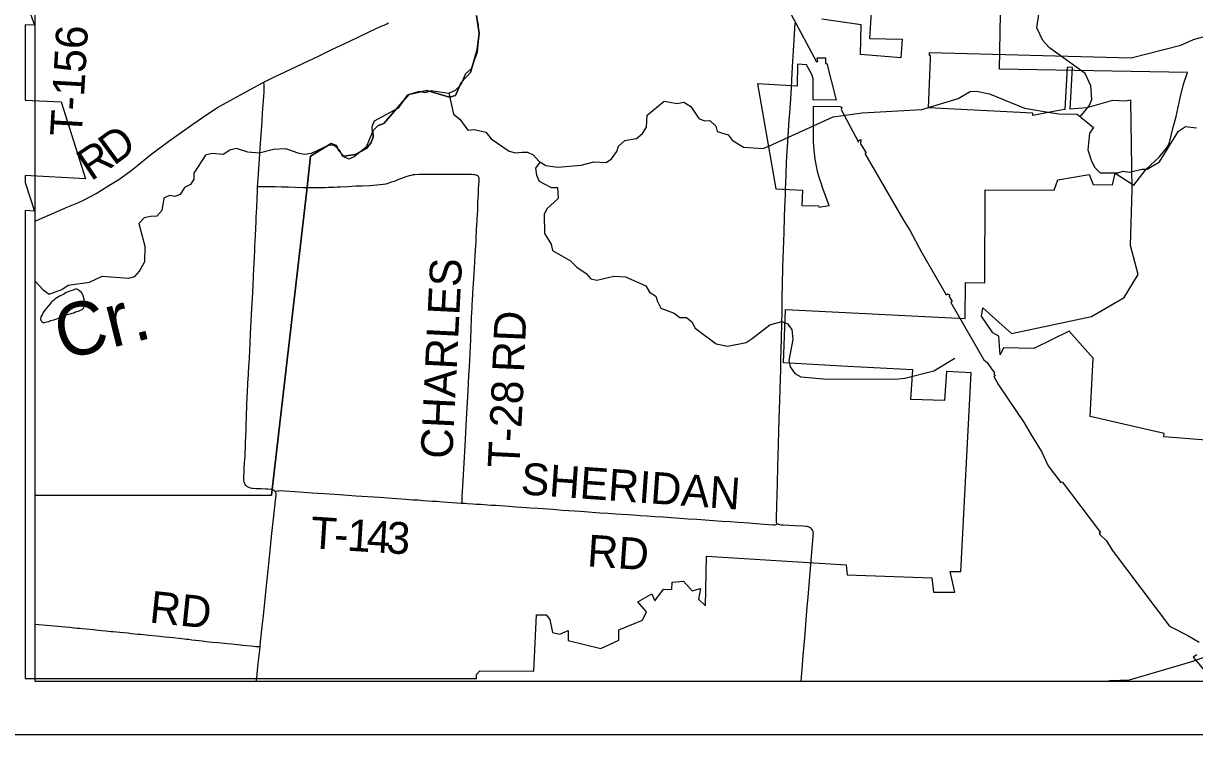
# Model space of a CAD drawing. Extents: x -5.4 to 49.9, y 13.2 to 48.4.
# Drawn here: x 26.257 to 28.351, y 40.548 to 41.82 of the extents above; entities that cross this region are included whole.
import ezdxf

# ---------------------------------------------------------------- set-up
doc = ezdxf.new("R2010")
doc.units = 0
for name, color, linetype in [('GM_X_Corporation', 7, 'Continuous'), ('GM_X_County_Road', 7, 'Continuous'), ('GM_X_County_Road_Text', 7, 'Continuous'), ('GM_X_Minor_Lake', 7, 'Continuous'), ('GM_X_Minor_River', 7, 'Continuous'), ('GM_X_Minor_River_Text', 7, 'Continuous'), ('GM_X_Township', 7, 'Continuous'), ('GM_X_Township_Road', 7, 'Continuous'), ('GM_X_Township_Road_Text', 7, 'Continuous'), ('SH_Data', 7, 'Continuous')]:
    doc.layers.add(name, color=color, linetype=linetype)

msp = doc.modelspace()

# ---------------------------------------------------------------- linework, layer by layer
at = {"layer": 'GM_X_Corporation'}
for p, q in [((26.2599, 41.8176), (26.2599, 41.683)), ((26.2599, 41.5479), (26.2599, 41.5354))]:
    msp.add_line(p, q, dxfattribs=at)
for points in [[(27.5529, 41.9806), (27.6747, 41.7515), (27.6772, 41.7529), (27.676, 41.7586), (27.6911, 41.7589), (27.6913, 41.7487), (27.6932, 41.7487), (27.7103, 41.6829), (27.6692, 41.6836), (27.6692, 41.7209), (27.6667, 41.7291), (27.6568, 41.7463), (27.6411, 41.7474), (27.6404, 41.7082), (27.5693, 41.7119), (27.6023, 41.5246), (27.65, 41.5221), (27.649, 41.4943), (27.6788, 41.4937), (27.6791, 41.4915), (27.6974, 41.4944), (27.6862, 41.525), (27.6836, 41.5326), (27.6809, 41.5412), (27.6776, 41.553), (27.675, 41.5646), (27.6727, 41.5771), (27.6712, 41.5883), (27.67, 41.6006), (27.6695, 41.6086), (27.6693, 41.6212), (27.6693, 41.6722), (27.7164, 41.6714), (27.7204, 41.6701), (27.7192, 41.6663), (27.7503, 41.6079), (27.7505, 41.6106), (27.7543, 41.6127), (27.7538, 41.6049), (27.7638, 41.5889), (27.7613, 41.5875), (27.8303, 41.4681), (27.8424, 41.4494), (27.8622, 41.4122), (27.9068, 41.335), (27.9092, 41.3365), (27.9125, 41.3346), (27.9122, 41.3316), (27.9173, 41.3228), (27.9149, 41.3213), (27.9741, 41.2188), (27.9802, 41.214), (27.9892, 41.2007), (27.9927, 41.1967), (27.9929, 41.1925), (27.9943, 41.1901), (27.9919, 41.1886), (28.0004, 41.1739), (28.0464, 41.1057), (28.0586, 41.0846), (28.0774, 41.0546), (28.0894, 41.0288), (28.112, 40.9989), (28.1142, 41.0006), (28.1826, 40.9099), (28.1804, 40.9082), (28.1817, 40.9063), (28.1938, 40.8946), (28.2037, 40.8782), (28.3063, 40.7422), (28.3387, 40.7257), (28.3592, 40.7138)], [(26.2599, 41.8637), (26.2765, 41.8168), (26.2599, 41.8176)], [(27.0672, 40.6483), (27.067, 40.6559), (27.0731, 40.6623), (27.1697, 40.6617), (27.1741, 40.7625), (27.1917, 40.7624), (27.1979, 40.754), (27.2027, 40.731), (27.2161, 40.7278), (27.2309, 40.7343), (27.2311, 40.7163), (27.2892, 40.702), (27.3213, 40.7172), (27.3213, 40.7356), (27.3639, 40.7528), (27.3708, 40.768), (27.3554, 40.7859), (27.3805, 40.7999), (27.3856, 40.7872), (27.4014, 40.8083), (27.416, 40.8079), (27.4169, 40.8211), (27.4372, 40.8226), (27.4524, 40.8052), (27.4673, 40.8095), (27.464, 40.7904), (27.4764, 40.7787), (27.4782, 40.8672), (27.7277, 40.8517), (27.7296, 40.8338), (27.881, 40.8285), (27.8843, 40.8029), (27.9224, 40.8032), (27.9139, 40.84), (27.9328, 40.8399), (27.9518, 41.1954), (27.9072, 41.1976), (27.9036, 41.1455), (27.8438, 41.1476), (27.8475, 41.2006), (27.7309, 41.2063), (27.6157, 41.2134), (27.6195, 41.3086), (27.9408, 41.2927), (27.9411, 41.3566), (27.9761, 41.3564), (27.9768, 41.5223), (28.0999, 41.5218), (28.1066, 41.5402), (28.1625, 41.55), (28.1694, 41.5322), (28.2045, 41.5317), (28.2093, 41.5524), (28.2425, 41.5308), (28.2645, 41.5598), (28.2876, 41.5808), (28.3024, 41.5995), (28.3064, 41.6075), (28.3123, 41.6322), (28.318, 41.6538), (28.3252, 41.6869), (28.331, 41.7114), (28.3382, 41.7321), (28.0022, 41.7383), (28.0047, 41.8708)], [(27.7742, 41.8691), (27.7695, 41.7935), (27.8282, 41.7919), (27.8255, 41.7585), (27.7538, 41.7648), (27.7547, 41.8177), (27.6842, 41.8275)], [(28.8307, 41.0387), (28.2962, 41.0805), (28.2965, 41.0867), (28.1644, 41.1172), (28.1698, 41.2214), (28.1265, 41.2695), (28.0635, 41.2388), (28.0091, 41.2397), (28.0034, 41.2274), (28.001, 41.2608), (27.9905, 41.2669), (27.9697, 41.2967), (27.9723, 41.3118), (28.0237, 41.2655), (28.1665, 41.2959), (28.2251, 41.3297), (28.25, 41.3713), (28.2362, 41.4231), (28.2396, 41.5224), (28.2368, 41.683), (28.2268, 41.6809), (28.2043, 41.6824), (28.1586, 41.6693), (28.1286, 41.6667), (28.1325, 41.7414), (28.1231, 41.7421), (28.1191, 41.666), (28.1112, 41.6653), (28.0616, 41.6557), (28.0617, 41.6595), (27.8755, 41.6692), (27.8785, 41.757), (27.8786, 41.7627), (27.8771, 41.7627), (27.8771, 41.7684), (28.2378, 41.7585), (28.3264, 41.7813), (28.349, 41.7916), (28.5206, 41.839)], [(26.2599, 41.683), (26.3243, 41.6802), (26.3679, 41.5423), (26.2599, 41.5479)], [(26.2599, 41.5354), (26.2766, 41.4846), (26.2599, 41.4853)], [(26.2599, 41.4853), (26.2599, 40.6483), (27.0672, 40.6483)], [(28.3549, 40.6908), (28.3487, 40.6869), (28.3802, 40.6489)]]:
    msp.add_lwpolyline(points, dxfattribs=at)
at = {"layer": 'GM_X_County_Road'}
for points in [[(26.6868, 41.7152), (26.7057, 41.7248), (26.7552, 41.7481), (26.7856, 41.7623), (26.8085, 41.7733), (26.8394, 41.788), (26.8765, 41.8055), (26.8967, 41.815), (26.9019, 41.8171), (26.9069, 41.8196), (26.9096, 41.8212)], [(27.6055, 40.9251), (27.6049, 40.9256), (27.6042, 40.9264), (27.6037, 40.9274), (27.6034, 40.9285), (27.6032, 40.9298), (27.6032, 40.932), (27.6034, 40.9363), (27.6053, 40.9972), (27.6061, 41.027), (27.6072, 41.0674), (27.6084, 41.1133), (27.6093, 41.1462), (27.6103, 41.1841), (27.6109, 41.2015), (27.6114, 41.2177), (27.6118, 41.2363), (27.6122, 41.2562), (27.6129, 41.2841), (27.6133, 41.3027), (27.6135, 41.3176), (27.6138, 41.3301), (27.6142, 41.353), (27.615, 41.3841), (27.6169, 41.4462), (27.6179, 41.4741), (27.6184, 41.4903), (27.6193, 41.5139), (27.6197, 41.525), (27.62, 41.535), (27.6205, 41.5498), (27.6213, 41.5703), (27.6219, 41.5833), (27.6228, 41.5994), (27.6246, 41.6273), (27.6262, 41.6478), (27.627, 41.6602), (27.6282, 41.6763), (27.63, 41.7042), (27.631, 41.7196), (27.6315, 41.7302), (27.6322, 41.7426), (27.6337, 41.7711), (27.6367, 41.8207)], [(26.2771, 41.4664), (26.2805, 41.4678), (26.3363, 41.492), (26.3541, 41.4995), (26.3665, 41.5054), (26.3742, 41.5093), (26.3868, 41.5162), (26.4096, 41.5301), (26.4276, 41.5413), (26.4383, 41.5487), (26.4517, 41.5589), (26.484, 41.5851), (26.4982, 41.5961), (26.5167, 41.6097), (26.5599, 41.6401), (26.5866, 41.6582), (26.6037, 41.6696), (26.6143, 41.6759), (26.6633, 41.7028), (26.6858, 41.7147), (26.6868, 41.7152)], [(26.6756, 41.5279), (26.6764, 41.5423), (26.6788, 41.5782), (26.6808, 41.6055), (26.6824, 41.6289), (26.6835, 41.6453), (26.6846, 41.6594), (26.6868, 41.6903), (26.6872, 41.6973), (26.6874, 41.7027), (26.6874, 41.7071), (26.6872, 41.7095), (26.6868, 41.7152)], [(26.663, 40.9891), (26.6629, 40.9892), (26.6606, 40.9899), (26.6588, 40.9907), (26.6576, 40.9912), (26.6567, 40.9918), (26.6556, 40.9927), (26.6544, 40.9938), (26.6533, 40.9953), (26.6525, 40.9969), (26.652, 40.9984), (26.6515, 40.9999), (26.6512, 41.0023), (26.6511, 41.0069), (26.6512, 41.0104), (26.6515, 41.016), (26.6518, 41.0253), (26.6524, 41.034), (26.6529, 41.0408), (26.6532, 41.0445), (26.6541, 41.0693), (26.655, 41.0942), (26.6553, 41.1016), (26.6554, 41.1059), (26.6555, 41.1121), (26.6557, 41.1158), (26.6566, 41.1394), (26.657, 41.1499), (26.6589, 41.1871), (26.659, 41.1896), (26.6594, 41.1951), (26.6595, 41.1982), (26.6598, 41.2025), (26.66, 41.2068), (26.6603, 41.213), (26.6608, 41.2216), (26.6615, 41.2353), (26.6622, 41.2489), (26.6629, 41.2644), (26.6641, 41.288), (26.6647, 41.3004), (26.6668, 41.3389), (26.6674, 41.3519), (26.6682, 41.3674), (26.6689, 41.3817), (26.6694, 41.3916), (26.6705, 41.414), (26.6709, 41.422), (26.6714, 41.4313), (26.6719, 41.4394), (26.6725, 41.4543), (26.6729, 41.4648), (26.6733, 41.4735), (26.6739, 41.4903), (26.6746, 41.507), (26.6752, 41.52), (26.6756, 41.5279)], [(26.7062, 40.9837), (26.7053, 40.9846), (26.7042, 40.9853), (26.7029, 40.9858), (26.702, 40.9862), (26.7005, 40.9866), (26.699, 40.9868), (26.694, 40.9871), (26.6902, 40.9873), (26.6822, 40.9875), (26.6728, 40.9879), (26.6672, 40.9884), (26.6653, 40.9886), (26.663, 40.9891)], [(26.68, 40.7056), (26.6809, 40.7144), (26.6838, 40.7416), (26.6859, 40.7608), (26.6896, 40.7972), (26.6931, 40.8312), (26.6967, 40.8652), (26.7005, 40.9023), (26.7051, 40.9449), (26.7076, 40.9672), (26.7086, 40.9759), (26.7086, 40.9778), (26.7085, 40.979), (26.7083, 40.9801), (26.7079, 40.9814), (26.7071, 40.9826), (26.7063, 40.9836), (26.7062, 40.9837)], [(27.6475, 40.6437), (27.6493, 40.6653), (27.6513, 40.6895), (27.6538, 40.7211), (27.6584, 40.7768), (27.6598, 40.7941), (27.6646, 40.8523), (27.6671, 40.8814), (27.669, 40.9018), (27.6691, 40.9055), (27.6693, 40.9079), (27.6691, 40.9096), (27.6688, 40.9114), (27.6685, 40.9124), (27.6677, 40.914), (27.6667, 40.9156), (27.6653, 40.9171), (27.6648, 40.9175), (27.6636, 40.9183), (27.662, 40.9192), (27.6602, 40.9199), (27.6585, 40.9203), (27.6564, 40.9207), (27.6513, 40.9211), (27.6369, 40.9216), (27.6152, 40.9227), (27.6115, 40.9231), (27.6092, 40.9234), (27.6075, 40.924), (27.6066, 40.9244), (27.6057, 40.9249), (27.6055, 40.9251)], [(26.6735, 40.6437), (26.6767, 40.6755), (26.6793, 40.699), (26.68, 40.7056)]]:
    msp.add_lwpolyline(points, dxfattribs=at)
at = {"layer": 'GM_X_Minor_Lake'}
msp.add_lwpolyline([(26.3518, 41.3455), (26.3331, 41.339), (26.3285, 41.3356), (26.3228, 41.3331), (26.3193, 41.3312), (26.3166, 41.3294), (26.3132, 41.3268), (26.3105, 41.3246), (26.3085, 41.3231), (26.3062, 41.3208), (26.3039, 41.3179), (26.3012, 41.3145), (26.2981, 41.3107), (26.2954, 41.3074), (26.2922, 41.3033), (26.2907, 41.2999), (26.2891, 41.2972), (26.2879, 41.2954), (26.2871, 41.292), (26.2882, 41.2889), (26.2901, 41.2866), (26.2919, 41.2854), (26.2946, 41.2854), (26.2988, 41.2864), (26.3022, 41.2871), (26.306, 41.2886), (26.311, 41.29), (26.3167, 41.2918), (26.3221, 41.294), (26.3293, 41.2969), (26.3351, 41.2994), (26.3404, 41.3009), (26.3438, 41.3019), (26.3469, 41.3026), (26.35, 41.3041), (26.3526, 41.3048), (26.3549, 41.3055), (26.3568, 41.3063), (26.3587, 41.3074), (26.361, 41.3077), (26.3633, 41.3099), (26.3649, 41.3118), (26.3653, 41.3137), (26.3661, 41.3167), (26.3658, 41.3201), (26.3655, 41.3239), (26.3655, 41.327), (26.3648, 41.3289), (26.3645, 41.3312), (26.3637, 41.3331), (26.363, 41.335), (26.3619, 41.3369), (26.3604, 41.3392), (26.3548, 41.3439), (26.3526, 41.3451), (26.3518, 41.3455)], dxfattribs=at)
at = {"layer": 'GM_X_Minor_River'}
for points in [[(27.0691, 41.8219), (27.0714, 41.8017), (27.0682, 41.7687), (27.0575, 41.7389), (27.0476, 41.7303), (27.0381, 41.71), (27.0289, 41.7003), (27.0171, 41.6951), (26.986, 41.6994), (26.975, 41.6961), (26.9644, 41.6986), (26.9431, 41.6921), (26.9268, 41.6684), (26.884, 41.6455), (26.88, 41.6353), (26.8802, 41.6251), (26.8696, 41.5991), (26.8485, 41.5815), (26.8386, 41.5775), (26.8276, 41.5826), (26.8225, 41.5926), (26.812, 41.6026), (26.8018, 41.6016), (26.7716, 41.5876), (26.7594, 41.5855), (26.7496, 41.5876), (26.7258, 41.5959), (26.7042, 41.5944), (26.6783, 41.5879), (26.6582, 41.5897), (26.6379, 41.5965), (26.6261, 41.5933), (26.6142, 41.5855), (26.5941, 41.5877), (26.5827, 41.5844), (26.5614, 41.5521), (26.5616, 41.5419), (26.5554, 41.5321), (26.5447, 41.5266), (26.5373, 41.5141), (26.5277, 41.5105), (26.5179, 41.5125), (26.508, 41.5078), (26.5046, 41.4854), (26.4953, 41.4757), (26.484, 41.4747), (26.4729, 41.4722), (26.4633, 41.4621), (26.474, 41.4217), (26.4733, 41.3931)], [(28.1463, 41.6532), (28.1627, 41.6728), (28.167, 41.6842), (28.1655, 41.7085), (28.1552, 41.7306), (28.0918, 41.7768), (28.0799, 41.7898), (28.0692, 41.812), (28.0726, 41.837)], [(27.0175, 41.6953), (27.026, 41.6578), (27.0372, 41.6489), (27.0517, 41.6293), (27.0631, 41.6303), (27.0839, 41.6254), (27.0932, 41.6139), (27.1254, 41.5918), (27.1368, 41.5889), (27.1486, 41.5899), (27.158, 41.5901), (27.1686, 41.5854), (27.1786, 41.5739), (27.1907, 41.5661), (27.2118, 41.5631), (27.2544, 41.5667), (27.2768, 41.5724), (27.2988, 41.5717), (27.3084, 41.578), (27.3177, 41.5911), (27.3209, 41.6009), (27.3324, 41.6106), (27.3529, 41.6145), (27.3637, 41.6235), (27.3707, 41.6347), (27.3722, 41.6563), (27.4025, 41.6809), (27.4259, 41.6768), (27.4377, 41.6793), (27.4501, 41.6715), (27.4646, 41.65), (27.4744, 41.6461), (27.4843, 41.6467), (27.4947, 41.6366), (27.4972, 41.6267), (27.5172, 41.6211), (27.5239, 41.6112), (27.5446, 41.5987), (27.5794, 41.5963), (27.5909, 41.601), (27.7047, 41.6532), (27.7567, 41.6604), (27.8634, 41.666), (27.9285, 41.6859), (27.9496, 41.6985), (27.9613, 41.699), (27.984, 41.6941), (28.0469, 41.6689), (28.0965, 41.6602), (28.1082, 41.6585), (28.1408, 41.6576), (28.1704, 41.634), (28.163, 41.6239), (28.1599, 41.5943), (28.1664, 41.5737), (28.1727, 41.5622), (28.1824, 41.553), (28.2139, 41.5529), (28.2234, 41.5561), (28.2348, 41.5541), (28.2565, 41.5598), (28.266, 41.5593), (28.2881, 41.5726), (28.3224, 41.6275), (28.3346, 41.6357), (28.3543, 41.6335)], [(27.1808, 41.5725), (27.1724, 41.5611), (27.1741, 41.5485), (27.1792, 41.5378), (27.2007, 41.5269), (27.2117, 41.5267), (27.2129, 41.5069), (27.1925, 41.4883), (27.1878, 41.4785), (27.1884, 41.4443), (27.2003, 41.4251), (27.2027, 41.4141), (27.2351, 41.3958), (27.2465, 41.384)], [(26.2771, 41.3596), (26.2922, 41.3438), (26.3031, 41.3361), (26.3256, 41.3445), (26.337, 41.3523), (26.3747, 41.3572), (26.3979, 41.3679), (26.4449, 41.3646), (26.456, 41.3675), (26.4644, 41.3772), (26.4733, 41.3931)], [(27.2465, 41.384), (27.2632, 41.373), (27.2714, 41.3634), (27.282, 41.361), (27.3128, 41.3682), (27.3333, 41.3667), (27.3695, 41.3511), (27.3766, 41.3396), (27.3875, 41.3326), (27.3904, 41.3231), (27.3964, 41.3109), (27.4205, 41.3018), (27.4307, 41.2945), (27.4424, 41.2944), (27.4522, 41.2863), (27.4581, 41.2752), (27.4957, 41.247), (27.5158, 41.2429), (27.5489, 41.2497), (27.5599, 41.2564), (27.5913, 41.2814), (27.6127, 41.2872), (27.6228, 41.2829), (27.6307, 41.2729), (27.6328, 41.2551), (27.6255, 41.2176), (27.6276, 41.2062), (27.6362, 41.1943), (27.6471, 41.1881), (27.6941, 41.184), (27.8216, 41.1847), (27.833, 41.186), (27.8847, 41.1987), (27.9225, 41.2217)], [(28.1943, 40.6437), (28.1997, 40.6449), (28.2347, 40.6464), (28.3443, 40.6784), (28.3763, 40.6897)]]:
    msp.add_lwpolyline(points, dxfattribs=at)
at = {"layer": 'GM_X_Township'}
msp.add_line((26.2771, 45.1783), (26.2771, 40.9761), dxfattribs=at)
for points in [[(26.2771, 40.9761), (26.7007, 40.9762), (26.7634, 41.5221), (26.7704, 41.5826), (26.8071, 41.6057), (26.8169, 41.6021), (26.8206, 41.5922), (26.8299, 41.5826), (26.8501, 41.5858), (26.8703, 41.5965), (26.8788, 41.607), (26.882, 41.6173), (26.8817, 41.6279), (26.891, 41.6376), (26.9012, 41.6409), (26.9459, 41.6928), (26.9779, 41.7004), (27.0187, 41.6881), (27.0297, 41.6914), (27.0395, 41.7144), (27.0564, 41.7324), (27.0679, 41.7737), (27.0717, 41.8029), (27.0668, 41.8344)], [(27.0668, 41.8344), (27.0717, 41.8029), (27.0679, 41.7737), (27.0564, 41.7324), (27.0395, 41.7144), (27.0297, 41.6914), (27.0187, 41.6881), (26.9779, 41.7004), (26.9459, 41.6928), (26.9012, 41.6409), (26.891, 41.6376), (26.8817, 41.6279), (26.882, 41.6173), (26.8788, 41.607), (26.8703, 41.5965), (26.8501, 41.5858), (26.8299, 41.5826), (26.8206, 41.5922), (26.8169, 41.6021), (26.8071, 41.6057), (26.7704, 41.5826), (26.7634, 41.5221), (26.7007, 40.9762), (26.2771, 40.9761)], [(26.2771, 40.9761), (26.2771, 40.6437), (28.3741, 40.6437)]]:
    msp.add_lwpolyline(points, dxfattribs=at)
at = {"layer": 'GM_X_Township_Road'}
for points in [[(27.0717, 41.5362), (27.0715, 41.5415), (27.0715, 41.5437), (27.0714, 41.5444), (27.0711, 41.5452), (27.0703, 41.5465), (27.0694, 41.5473), (27.0684, 41.548), (27.0676, 41.5484), (27.0667, 41.5487), (27.0642, 41.5492), (27.062, 41.5495), (27.0581, 41.5498), (27.0516, 41.55), (27.0413, 41.5499), (27.0334, 41.55), (27.0214, 41.5497), (27.0081, 41.5497), (26.9913, 41.5499), (26.9827, 41.5498), (26.9764, 41.5498), (26.9644, 41.5499), (26.9568, 41.5495), (26.9539, 41.5491), (26.9501, 41.5483), (26.9465, 41.5474), (26.9447, 41.5469), (26.9423, 41.5462), (26.9388, 41.5451), (26.9349, 41.5437), (26.9276, 41.5408), (26.9239, 41.5392), (26.9199, 41.5376), (26.9152, 41.536), (26.9117, 41.5348), (26.9082, 41.5337), (26.905, 41.5329), (26.8998, 41.5319), (26.8946, 41.5313), (26.8888, 41.5307), (26.8769, 41.5299), (26.8628, 41.5294), (26.8513, 41.5289), (26.8373, 41.5281), (26.8239, 41.5275), (26.8177, 41.5272), (26.8122, 41.527), (26.8022, 41.5267), (26.7966, 41.5264), (26.7917, 41.5263), (26.788, 41.5262), (26.7826, 41.526), (26.7753, 41.5259)], [(26.7753, 41.5259), (26.773, 41.5259), (26.7681, 41.5259), (26.757, 41.526), (26.7427, 41.5265), (26.7309, 41.5271), (26.7185, 41.5275), (26.7067, 41.5279), (26.7033, 41.5279), (26.6998, 41.528), (26.695, 41.528), (26.6897, 41.528), (26.6852, 41.5279), (26.6802, 41.5279), (26.6756, 41.5279)], [(27.0412, 40.9623), (27.0414, 40.9684), (27.0415, 40.9728), (27.0432, 41.0026), (27.0467, 41.0646), (27.0493, 41.1124), (27.0521, 41.1633), (27.0535, 41.1907), (27.0544, 41.2062), (27.0556, 41.2296), (27.0561, 41.2418), (27.0567, 41.2546), (27.0572, 41.2738), (27.0574, 41.2788), (27.0579, 41.2881), (27.0582, 41.293), (27.0588, 41.3042), (27.0592, 41.3104), (27.0594, 41.3154), (27.06, 41.3271), (27.0604, 41.3333), (27.0606, 41.3377), (27.0627, 41.3724), (27.0644, 41.4047), (27.0659, 41.4239), (27.0662, 41.4283), (27.0663, 41.4307), (27.0665, 41.4338), (27.0665, 41.4357), (27.0665, 41.4394), (27.0665, 41.4419), (27.0666, 41.4425), (27.0667, 41.4437), (27.0671, 41.4536), (27.0673, 41.4573), (27.0681, 41.4703), (27.0686, 41.4787), (27.0691, 41.4856), (27.0693, 41.4933), (27.0696, 41.5002), (27.0701, 41.5075), (27.0703, 41.5137), (27.0705, 41.5187), (27.0708, 41.5237), (27.0714, 41.5327), (27.0717, 41.5362)], [(26.7062, 40.9837), (26.711, 40.9842), (26.7135, 40.9845), (26.7165, 40.9847), (26.7245, 40.9844), (26.7425, 40.9832), (26.7732, 40.9809), (26.7945, 40.9794), (26.8218, 40.9774), (26.8515, 40.9752), (26.8937, 40.9726), (26.9247, 40.9704), (26.9408, 40.9692), (26.9532, 40.9684), (26.9625, 40.9679), (26.9711, 40.9672), (26.9804, 40.9666), (26.9885, 40.966), (26.9959, 40.9655), (27.0065, 40.9647), (27.0236, 40.9635), (27.032, 40.9629), (27.0393, 40.9624), (27.0412, 40.9623)], [(27.0412, 40.9623), (27.0461, 40.962), (27.0511, 40.9617), (27.0604, 40.9611), (27.0666, 40.9606), (27.074, 40.9601), (27.0932, 40.9588), (27.1013, 40.9583), (27.1254, 40.9566), (27.1372, 40.9558), (27.1477, 40.955), (27.157, 40.9544), (27.1638, 40.9539), (27.1768, 40.9531), (27.2034, 40.9512), (27.2096, 40.9506), (27.2208, 40.9498), (27.2529, 40.9476), (27.2877, 40.9451), (27.3016, 40.9443), (27.3162, 40.9432), (27.3261, 40.9425), (27.3385, 40.9417), (27.3472, 40.9411), (27.3596, 40.9403), (27.372, 40.9394), (27.3856, 40.9385), (27.4005, 40.9375), (27.4153, 40.9364), (27.4308, 40.9354), (27.4456, 40.9343), (27.4612, 40.9333), (27.476, 40.9322), (27.4909, 40.9311), (27.5058, 40.9302), (27.5205, 40.9291), (27.5352, 40.9281), (27.5541, 40.9268), (27.5813, 40.9248), (27.5975, 40.9237), (27.5989, 40.9236), (27.6005, 40.9237), (27.6024, 40.924), (27.6043, 40.9246), (27.6055, 40.9251)], [(26.2771, 40.7456), (26.3053, 40.7432), (26.3313, 40.7408), (26.3399, 40.7401), (26.3479, 40.7394), (26.3528, 40.7389), (26.3572, 40.7384), (26.3621, 40.7381), (26.3689, 40.7373), (26.3825, 40.7361), (26.3856, 40.7358), (26.3967, 40.7347), (26.4041, 40.7339), (26.4139, 40.7329), (26.4175, 40.7326), (26.4292, 40.7315), (26.436, 40.7308), (26.444, 40.73), (26.4502, 40.7293), (26.4619, 40.7281), (26.4662, 40.7277), (26.4811, 40.7262), (26.4946, 40.7248), (26.5101, 40.7232), (26.5237, 40.7218), (26.5354, 40.7205), (26.5484, 40.7192), (26.5527, 40.7187), (26.5582, 40.718), (26.5644, 40.7173), (26.5712, 40.7164), (26.5767, 40.7158), (26.5835, 40.715), (26.5884, 40.7144), (26.5946, 40.7138), (26.605, 40.7128), (26.6218, 40.7111), (26.6295, 40.7103), (26.6395, 40.7092), (26.6491, 40.7081), (26.664, 40.7068), (26.6727, 40.7061), (26.6768, 40.7058), (26.68, 40.7056)]]:
    msp.add_lwpolyline(points, dxfattribs=at)
at = {"layer": 'SH_Data'}
msp.add_line((26.1653, 40.5483), (33.1653, 40.5483), dxfattribs=at)

# ---------------------------------------------------------------- texts
at = {"layer": 'GM_X_County_Road_Text'}
for s, rotation, p in [('D', 36.3468, (26.4184, 41.5647)), ('R', 33.9055, (26.3776, 41.5372))]:
    msp.add_text(s, height=0.0568, rotation=rotation, dxfattribs=at).set_placement(p)
at = {"layer": 'GM_X_Minor_River_Text'}
msp.add_text('Cr.', height=0.09469, rotation=14.0537, dxfattribs=at).set_placement((26.3261, 41.2177))
at = {"layer": 'GM_X_Township_Road_Text'}
for s, height, rotation, p in [('T-156', 0.05682, 86.6343, (26.361, 41.617)), ('CHARLES', 0.05682, 87.1663, (27.0236, 41.0404)), ('RD', 0.05682, 87.5301, (27.1518, 41.1954)), ('T-28', 0.05682, 87.1555, (27.1436, 41.0244)), ('SHERIDAN', 0.05682, 355.9622, (27.1451, 40.9782)), ('T', 0.0568, 356.2646, (26.7687, 40.8817)), ('1', 0.0568, 356.2978, (26.8344, 40.8774)), ('4', 0.0568, 356.3651, (26.8694, 40.8752)), ('3', 0.0568, 356.6705, (26.9047, 40.8729)), ('-', 0.0568, 356.2649, (26.8111, 40.8789)), ('RD', 0.05682, 356.1256, (27.2638, 40.8494)), ('RD', 0.05682, 354.0861, (26.4808, 40.749))]:
    msp.add_text(s, height=height, rotation=rotation, dxfattribs=at).set_placement(p)

doc.saveas('drawing.dxf')
